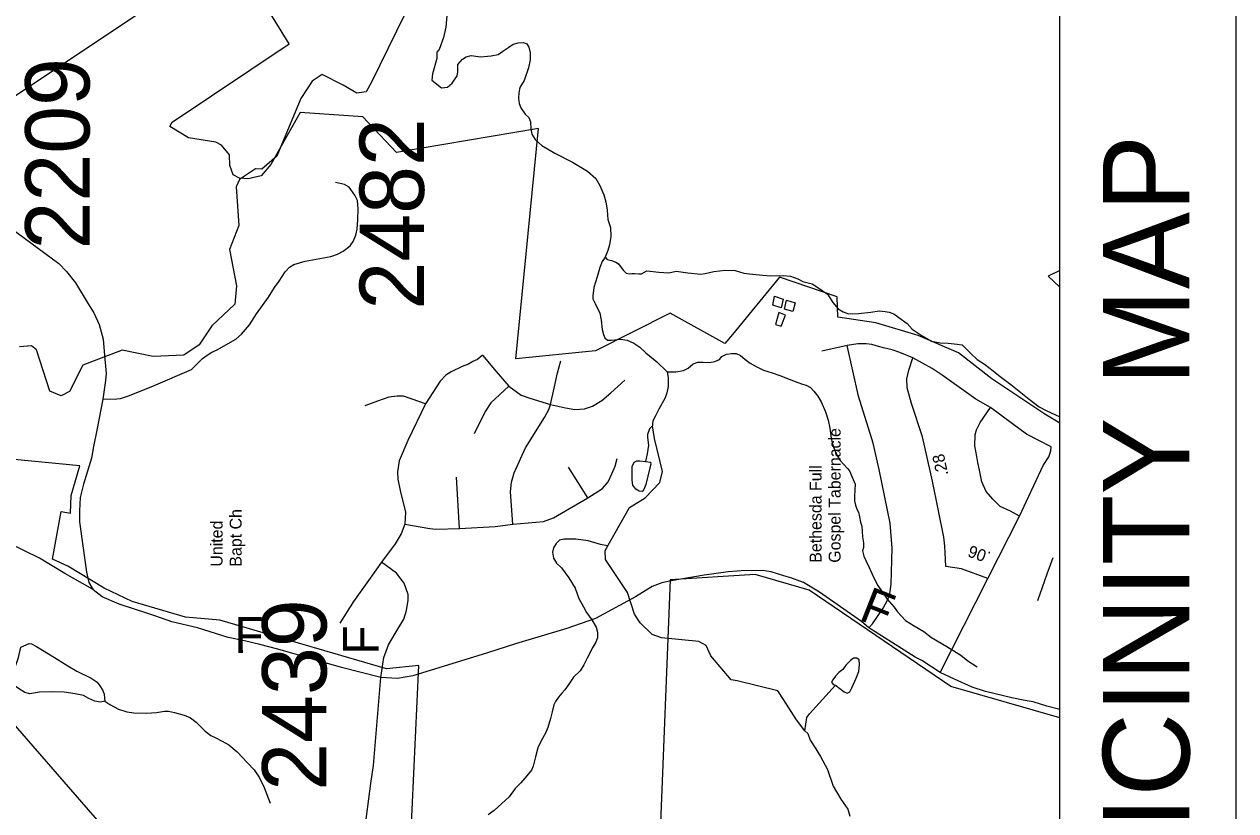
# Model space of a CAD drawing. Extents: x 1373043 to 1375788, y 550128 to 553055.
# Drawn here: x 1373360.4 to 1373623.1, y 550588.9 to 550759.4 of the extents above; entities that cross this region are included whole.
import ezdxf

# ---------------------------------------------------------------- set-up
doc = ezdxf.new("R2010")
doc.units = 0
for name, color, linetype in [('Old_Level_12', 7, 'Continuous'), ('Old_Level_17', 7, 'Continuous'), ('Old_Level_22', 7, 'Continuous'), ('Old_Level_32', 7, 'Continuous'), ('Old_Level_48', 7, 'Continuous'), ('Old_Level_50', 7, 'Continuous'), ('Old_Level_59', 7, 'Continuous'), ('Old_Level_62', 7, 'Continuous'), ('Prop Dimension', 7, 'Continuous'), ('Prop Dimension Text', 7, 'Continuous')]:
    doc.layers.add(name, color=color, linetype=linetype)

msp = doc.modelspace()

# ---------------------------------------------------------------- linework, layer by layer
at = {"layer": 'Old_Level_22'}
for p, q in [((1373400.86, 550641.82), (1373400.86, 550641.82)), ((1373530.72, 550642.67), (1373530.72, 550642.67))]:
    msp.add_line(p, q, dxfattribs=at)
at = {"layer": 'Old_Level_32'}
for p, q in [((1373538.88, 550689.74), (1373533.34, 550688.52)), ((1373454.83, 550650.13), (1373454.17, 550661.22)), ((1373482.61, 550656.73), (1373478.44, 550663.37)), ((1373569.36, 550639.28), (1373576.19, 550652.74)), ((1373559.03, 550618.87), (1373569.36, 550639.28))]:
    msp.add_line(p, q, dxfattribs=at)
for points in [[(1373328.03, 550758.48), (1373329.18, 550754.77), (1373331.08, 550744.1), (1373332.27, 550739.51), (1373332.66, 550737.41), (1373333.69, 550735.13), (1373334.26, 550733.77), (1373336.1, 550731.94), (1373337.95, 550730.2), (1373339.13, 550729.07), (1373349.95, 550720.77), (1373367.92, 550707.57), (1373369.63, 550705.81), (1373371.59, 550703.35), (1373374.3, 550698.81), (1373375.56, 550696.86), (1373376.72, 550694.35), (1373377.56, 550691.18), (1373377.85, 550687.6)], [(1373377.45, 550678.13), (1373380.49, 550678.2), (1373381.31, 550678.3), (1373383.27, 550678.94), (1373388.47, 550681.04), (1373396.69, 550684.56), (1373399.07, 550686.95), (1373399.91, 550687.57), (1373401.12, 550688.3), (1373402.27, 550688.84), (1373404.63, 550690.24), (1373406.31, 550691.16), (1373407.54, 550692.23), (1373409.25, 550694.29), (1373410.81, 550696.61), (1373413.41, 550700.27), (1373414.71, 550702.38), (1373415.68, 550703.75), (1373417.02, 550705.77), (1373417.97, 550706.75), (1373418.92, 550707.34), (1373421.38, 550708.07), (1373426.91, 550709.07), (1373428.33, 550709.61), (1373429.61, 550710.25), (1373431.13, 550711.42), (1373431.74, 550712.3), (1373432.31, 550713.67), (1373432.6, 550714.99), (1373432.74, 550717.09), (1373432.83, 550719.43), (1373432.69, 550721.19), (1373432.12, 550722.37), (1373430.89, 550724.08), (1373429.89, 550724.66), (1373427.9, 550725.15)], [(1373553.1, 550687.08), (1373550.26, 550688.25), (1373548.6, 550688.84), (1373546.75, 550689.28), (1373545.61, 550689.57), (1373544.19, 550690.01), (1373542.96, 550690.11), (1373541.2, 550690.13), (1373538.88, 550689.74)], [(1373377.85, 550687.6), (1373378.18, 550683.7), (1373378.05, 550682.16), (1373377.45, 550678.13)], [(1373459.81, 550687.69), (1373458.72, 550686.76), (1373457.72, 550686.3), (1373456.73, 550685.71), (1373455.4, 550685.22), (1373452.98, 550684.05), (1373451.84, 550683.36), (1373450.61, 550682.04), (1373447.44, 550677.11)], [(1373459.81, 550687.69), (1373462.79, 550684.12), (1373465.5, 550680.97)], [(1373543.57, 550628.57), (1373544.38, 550629.45), (1373546.65, 550632.82), (1373547.7, 550634.68), (1373548.08, 550635.9), (1373548.41, 550638.01), (1373548.64, 550645.8), (1373548.17, 550651.28), (1373545.8, 550662.88), (1373544.47, 550668.63), (1373541.3, 550678.82), (1373538.88, 550689.74)], [(1373474.55, 550676.98), (1373475.36, 550680.55), (1373476.07, 550683.88), (1373476.78, 550686.42)], [(1373560.21, 550641.84), (1373560.16, 550643.36), (1373560, 550646.28), (1373559.78, 550648.25), (1373557.32, 550660.39), (1373555.19, 550669.95), (1373552.77, 550677.2), (1373551.87, 550680.63), (1373551.82, 550682.53), (1373552.2, 550684.44), (1373553.1, 550687.08)], [(1373569.92, 550676.34), (1373566.74, 550678.17), (1373559.48, 550683.37), (1373557.3, 550684.8), (1373553.1, 550687.08)], [(1373474.55, 550676.98), (1373477.77, 550676.25), (1373479.81, 550675.91), (1373481.9, 550676.01), (1373483.65, 550676.59), (1373485.69, 550677.84), (1373487.59, 550679.5), (1373490.62, 550682.29)], [(1373465.5, 550680.97), (1373461.61, 550677.35), (1373460.38, 550675.49), (1373458.01, 550670.61)], [(1373465.5, 550680.97), (1373468.15, 550679.01), (1373470.05, 550678.33), (1373474.55, 550676.98)], [(1373377.45, 550678.13), (1373376.17, 550671.42), (1373375.43, 550667.9), (1373375.01, 550665.35), (1373373.3, 550659.68), (1373372.54, 550656.8), (1373372.44, 550653.89), (1373372.44, 550651.56), (1373373.96, 550640.62), (1373374.46, 550638.4), (1373375.41, 550636.79)], [(1373447.44, 550677.11), (1373444.54, 550678.16), (1373442.65, 550678.79), (1373441.27, 550678.79), (1373439.47, 550678.6), (1373437.05, 550677.67), (1373434.3, 550676.72)], [(1373447.44, 550677.11), (1373443.64, 550669.19), (1373441.75, 550664.79), (1373441.37, 550662.35), (1373441.46, 550660.78), (1373441.94, 550658.34), (1373443.08, 550653.65), (1373442.98, 550651.01)], [(1373466.4, 550651.01), (1373465.88, 550658.02), (1373466.11, 550660.12), (1373466.68, 550662.17), (1373469.15, 550667.6), (1373473.27, 550674.15), (1373474.17, 550675.91), (1373474.55, 550676.98)], [(1373576.19, 550652.74), (1373574.24, 550653.82), (1373572.01, 550654.84), (1373570.4, 550656.46), (1373568.98, 550658.12), (1373568.03, 550660.22), (1373567.51, 550662.76), (1373567.15, 550664.42), (1373566.93, 550665.69), (1373566.56, 550667.99), (1373566.61, 550670.44), (1373566.89, 550671.46), (1373567.7, 550673.07), (1373569.92, 550676.34)], [(1373583.11, 550667.82), (1373577.7, 550670.56), (1373574.72, 550672.81), (1373569.92, 550676.34)], [(1373576.19, 550652.74), (1373581.31, 550663.72), (1373582.54, 550665.67), (1373583.01, 550666.94), (1373583.11, 550667.82)], [(1373482.61, 550656.73), (1373485.83, 550658.8), (1373487.07, 550660.22), (1373487.83, 550661.93), (1373488.54, 550663.64), (1373488.96, 550665.3)], [(1373466.4, 550651.01), (1373473.04, 550651.64), (1373475.17, 550652.42), (1373482.61, 550656.73)], [(1373442.98, 550651.01), (1373442.18, 550648.93), (1373440.85, 550646.78), (1373437.91, 550642.77)], [(1373442.98, 550651.01), (1373448.39, 550650.13), (1373449.71, 550649.93), (1373454.83, 550650.13)], [(1373454.83, 550650.13), (1373462.51, 550650.52), (1373466.4, 550651.01)], [(1373375.41, 550636.79), (1373374.72, 550637.22), (1373369.24, 550640.36), (1373363.78, 550643.64), (1373357.11, 550646.91), (1373353.57, 550647.68), (1373352.78, 550647.81), (1373350.43, 550648.19), (1373347.78, 550648.18), (1373344.63, 550647.87), (1373343.61, 550647.64), (1373342.66, 550647.34), (1373341.51, 550646.73), (1373338.9, 550645.72), (1373337.63, 550645.12), (1373333.58, 550644), (1373322.27, 550642.97), (1373318.17, 550642.73)], [(1373583.46, 550643.74), (1373582.16, 550640.21), (1373580.15, 550634.42)], [(1373437.91, 550642.77), (1373435.44, 550639.35), (1373431.84, 550634.27), (1373428.9, 550629.57)], [(1373437.72, 550617.75), (1373438.38, 550622.14), (1373439.43, 550624.88), (1373440.85, 550627.33), (1373442.75, 550630.4), (1373443.34, 550632.33), (1373443.68, 550634.59), (1373443.68, 550635.76), (1373442.84, 550638.27), (1373441.13, 550640.42), (1373437.91, 550642.77)], [(1373543.57, 550628.57), (1373541.98, 550629.96), (1373532.85, 550636.27), (1373529.36, 550638.42), (1373526.67, 550639.42), (1373525.1, 550639.83), (1373522.38, 550640.67), (1373520.49, 550641.01), (1373515.89, 550640.91), (1373515, 550640.84), (1373513.04, 550640.67), (1373507.88, 550639.99), (1373500.67, 550638.78), (1373498.66, 550638.28), (1373496.59, 550637.54), (1373492.94, 550635.29), (1373484.32, 550630.58), (1373478.11, 550628.38), (1373466.97, 550625.05), (1373460.85, 550623.15), (1373444.68, 550618.16), (1373441.33, 550617.57), (1373437.72, 550617.75)], [(1373569.36, 550639.28), (1373563.67, 550641.33), (1373560.21, 550641.84)], [(1373437.72, 550617.75), (1373429.26, 550619.98), (1373415.41, 550623.9), (1373411.52, 550624.92), (1373408.23, 550625.7), (1373404.63, 550626.46), (1373398, 550628.55), (1373392.47, 550629.86), (1373388.98, 550631.07), (1373387.22, 550631.66), (1373381.01, 550633.67), (1373377.32, 550635.26), (1373375.41, 550636.79)], [(1373559.03, 550618.87), (1373555.04, 550621.44), (1373553.6, 550622.16), (1373551.99, 550623.2), (1373543.57, 550628.57)], [(1373433.95, 550582.11), (1373435.62, 550594.77), (1373436.13, 550598.71), (1373437.72, 550617.75)], [(1373584.98, 550610.88), (1373582.16, 550611.54), (1373579.17, 550612.52), (1373577.04, 550612.86), (1373574.53, 550613.35), (1373568.84, 550614.72), (1373565.95, 550615.69), (1373562.15, 550617.4), (1373559.03, 550618.87)]]:
    msp.add_lwpolyline(points, dxfattribs=at)
at = {"layer": 'Old_Level_48'}
for points in [[(1373524.15, 550704.61), (1373514.02, 550692.19), (1373512.31, 550690.18), (1373500.47, 550696.79), (1373484.28, 550688.61), (1373467.02, 550686.86), (1373471.9, 550736.81), (1373441.16, 550731.65), (1373433.88, 550739.36), (1373420.29, 550740.28), (1373413.94, 550729), (1373411.81, 550726.59), (1373409.02, 550725.89), (1373407.13, 550726.05), (1373405.77, 550726.77), (1373404.99, 550728.81), (1373404.97, 550731.14), (1373403.18, 550733.2), (1373402, 550733.85), (1373396.09, 550734.79), (1373391.99, 550737.27), (1373392.51, 550738.21), (1373417.89, 550755.2), (1373405.51, 550775.31), (1373351.12, 550739)], [(1373584.98, 550706.07), (1373582.46, 550704.79), (1373584.98, 550702.45)], [(1373584.98, 550672.97), (1373581.69, 550674.91), (1373574.37, 550679.8), (1373570.24, 550682.56), (1373562.98, 550688.22), (1373554.26, 550691.92), (1373545.04, 550694.7), (1373536.85, 550695.92), (1373536.67, 550700.34), (1373524.15, 550704.61)], [(1373444.19, 550581.38), (1373445.99, 550620.38), (1373438.95, 550619.66), (1373402.82, 550630.25), (1373395.39, 550630.86), (1373383.87, 550634.28), (1373377.76, 550637.19), (1373369.89, 550641.91), (1373366.59, 550643.47), (1373368.45, 550653.8), (1373370.47, 550653.45), (1373370.64, 550657.26), (1373372.48, 550663.67), (1373351.49, 550665.74)], [(1373584.98, 550609.04), (1373561.35, 550615.82), (1373530.64, 550636.75), (1373518.91, 550640.1), (1373500.48, 550638.99), (1373498.24, 550582.6)]]:
    msp.add_lwpolyline(points, dxfattribs=at)
at = {"layer": 'Old_Level_50'}
msp.add_line((1373377.84, 550687.6), (1373377.84, 550687.6), dxfattribs=at)
at = {"layer": 'Old_Level_59'}
for points in [[(1373446.58, 550769.04), (1373435.73, 550746.85), (1373434.56, 550744.79), (1373432.54, 550744.51), (1373429.59, 550746.25), (1373425.02, 550748.54), (1373422.86, 550747.06), (1373420.44, 550743.3), (1373415.2, 550730.84), (1373411.94, 550728.04), (1373410.59, 550728.07), (1373407.14, 550725.77), (1373406.38, 550724.2), (1373406.94, 550715.79), (1373404.97, 550710.59), (1373406.46, 550702.68), (1373406.07, 550698.74), (1373401.09, 550694.03), (1373398.39, 550689.9), (1373395.07, 550687.65), (1373388.41, 550687.38), (1373381.68, 550688.76), (1373373.17, 550685.48), (1373370.23, 550679.78), (1373368.46, 550678.89), (1373365.99, 550679.87), (1373363.07, 550688.85), (1373362.05, 550689.67), (1373359.45, 550689.51)], [(1373452.12, 550762.11), (1373451.87, 550758.78), (1373451.31, 550756.59), (1373450.43, 550753.96), (1373449.89, 550753.38), (1373449.89, 550752.03), (1373448.95, 550748.67), (1373448.81, 550747.33), (1373450.87, 550745.68), (1373452.24, 550745.77), (1373453.25, 550746.66), (1373454.32, 550748.27), (1373454.46, 550749.08), (1373454.48, 550750.72), (1373455.43, 550751.84), (1373456.22, 550752.39), (1373457.33, 550752.68), (1373459.37, 550752.39), (1373461.7, 550752.59), (1373463.16, 550752.87), (1373464.23, 550753.61), (1373465.51, 550754.46), (1373466.41, 550755.14), (1373467.5, 550755.43), (1373468.69, 550755.47), (1373469.38, 550755.2), (1373469.86, 550754.5), (1373470.14, 550753.23), (1373470.11, 550751.72), (1373469.76, 550749.96), (1373468.83, 550747.27), (1373467.92, 550745.71), (1373467.64, 550744.59), (1373467.57, 550743.39), (1373467.72, 550742.25), (1373468.07, 550741.3), (1373469.05, 550739.96), (1373469.81, 550739.18), (1373470.23, 550738.29), (1373470.25, 550736.72), (1373470.48, 550735.58), (1373471.21, 550734.43), (1373472.63, 550733.14), (1373475.49, 550731.5), (1373479.31, 550729.53), (1373482.55, 550727.57), (1373484.4, 550725.96), (1373485.2, 550724.49), (1373486.09, 550722.46), (1373486.5, 550720.94), (1373486.85, 550719.1), (1373486.99, 550717.08), (1373487.53, 550715.37), (1373487.61, 550713.41), (1373487.32, 550711.59), (1373486.99, 550710.34), (1373486.39, 550708.9)], [(1373486.39, 550708.9), (1373485.72, 550707.97), (1373485.26, 550706.72), (1373484.65, 550704.65), (1373483.9, 550702.33), (1373483.69, 550700.57), (1373483.72, 550699.88), (1373484.22, 550698.86), (1373485.24, 550696.82), (1373485.52, 550695.3), (1373485.74, 550693.22), (1373486.02, 550692.14), (1373486.32, 550691.44), (1373486.88, 550690.92), (1373487.78, 550690.91), (1373489.73, 550691.12), (1373491.17, 550690.9), (1373492.6, 550690.3), (1373493.91, 550689.45), (1373495.22, 550688.17), (1373497.56, 550686.23), (1373499.8, 550684.1)], [(1373499.8, 550684.1), (1373500.03, 550682.84), (1373500.04, 550680.88), (1373499.75, 550679.5), (1373499.37, 550678.44), (1373498.05, 550675.94), (1373497.2, 550674.39), (1373496.74, 550673.45), (1373496.67, 550672.76), (1373496.66, 550672.38)], [(1373529.66, 550606.25), (1373527.84, 550608.59), (1373525.05, 550612.99), (1373523.79, 550614.88), (1373514.98, 550617.03), (1373513.73, 550617.3), (1373509.28, 550622.47), (1373508.29, 550624.71), (1373506.67, 550625.61), (1373498.61, 550626.42), (1373496.6, 550627.14), (1373494, 550629.65), (1373492.74, 550631.54), (1373491.21, 550636.21), (1373486.45, 550643.4), (1373486.37, 550645.35), (1373491.63, 550654.68), (1373495.08, 550656.72), (1373498.25, 550660.06), (1373498.81, 550662.42), (1373497.11, 550669.64), (1373496.66, 550672.38)], [(1373529.66, 550606.25), (1373530.36, 550605.62), (1373530.8, 550604.19), (1373532.06, 550602.3), (1373532.51, 550601.58), (1373533.05, 550600.68), (1373534.58, 550597.81), (1373535.84, 550594.21), (1373537.46, 550591.43), (1373538.98, 550589.27), (1373539.43, 550587.75)]]:
    msp.add_lwpolyline(points, dxfattribs=at)
at = {"layer": 'Old_Level_62'}
for points in [[(1373486.39, 550708.9), (1373486.82, 550708.39), (1373487.74, 550708.18), (1373488.69, 550707.84), (1373489.31, 550707.45), (1373490.29, 550706.11), (1373490.92, 550705.46), (1373491.59, 550705.32), (1373492.16, 550705.37), (1373492.73, 550705.36), (1373493.68, 550705.28), (1373494.3, 550705.33), (1373495.4, 550705.94), (1373496.15, 550705.86), (1373498.03, 550705.7), (1373500.17, 550705.52), (1373501.81, 550705.87), (1373504.34, 550705.5), (1373507.1, 550705.25), (1373508.06, 550705.42), (1373509.95, 550705.82), (1373512.41, 550706.09), (1373514.56, 550706.04), (1373516.43, 550705.44), (1373518.31, 550705.21), (1373520.59, 550705.04), (1373522.29, 550704.87), (1373525.06, 550704.94), (1373526.58, 550704.79), (1373528.19, 550704.25), (1373529.27, 550703.66), (1373531.28, 550703.18), (1373532.5, 550702.33), (1373534.56, 550700.9), (1373535.72, 550699.11), (1373536.88, 550697.76), (1373537.95, 550697.05), (1373539.13, 550696.65), (1373541.33, 550696.73), (1373544, 550696.99), (1373545.76, 550697.26), (1373547.08, 550697.18), (1373547.95, 550696.97), (1373548.95, 550696.63), (1373550.07, 550695.85), (1373551.83, 550694.56), (1373552.92, 550693.34), (1373554.91, 550692.03), (1373557.11, 550690.73), (1373558.99, 550690.37), (1373560.74, 550690.27), (1373562.7, 550690.1), (1373563.76, 550689.9), (1373564.75, 550688.99), (1373565.68, 550688.03), (1373567.03, 550686.74), (1373568.66, 550685.76), (1373570.52, 550684.27), (1373572, 550683.04), (1373574.31, 550681.29), (1373578.33, 550678.12), (1373580.5, 550676.5), (1373582.01, 550675.71), (1373584.98, 550674.29)], [(1373522.73, 550698.5), (1373523.08, 550700.45), (1373524.95, 550699.84), (1373524.53, 550697.96), (1373522.73, 550698.5)], [(1373525.3, 550697.63), (1373525.7, 550699.57), (1373527.57, 550699.03), (1373527.04, 550697.15), (1373525.3, 550697.63)], [(1373524.07, 550696.9), (1373523.32, 550694.33), (1373524.58, 550693.99), (1373525.45, 550696.36), (1373524.07, 550696.9)], [(1373499.8, 550684.1), (1373501.68, 550684.06), (1373503.34, 550684.35), (1373504.36, 550684.83), (1373505.49, 550685.81), (1373506.45, 550686.17), (1373507.64, 550686.14), (1373509.04, 550686.12), (1373510.18, 550686.34), (1373511.14, 550686.76), (1373511.65, 550687.38), (1373512.72, 550687.93), (1373513.81, 550688.03), (1373514.76, 550688.01), (1373515.76, 550687.62), (1373516.68, 550686.84), (1373517.8, 550685.93), (1373519.1, 550685.21), (1373520.74, 550684.42), (1373522.61, 550683.82), (1373524.23, 550683.28), (1373526.31, 550682.48), (1373528.18, 550681.75), (1373529.18, 550681.41), (1373529.98, 550681.14), (1373530.93, 550680.68), (1373531.66, 550679.85), (1373532.52, 550678.76), (1373533.24, 550677.54), (1373534.15, 550675.38), (1373534.74, 550673.6), (1373535.09, 550671.83), (1373535.36, 550669.69), (1373535.59, 550668.67), (1373535.94, 550667.59), (1373536.73, 550665.81), (1373537.33, 550664.85), (1373538.14, 550663.96), (1373538.95, 550663.12), (1373539.38, 550662.61), (1373539.97, 550661.21), (1373540.58, 550659.68), (1373540.45, 550657.1), (1373540.43, 550656.09), (1373540.67, 550655.14), (1373540.97, 550654.32), (1373541.34, 550653.61), (1373541.55, 550652.6), (1373541.74, 550651.46), (1373542.03, 550650.57), (1373542.16, 550648.3), (1373542.4, 550646.98), (1373542.38, 550645.97), (1373542.15, 550645.22), (1373542.47, 550644.08), (1373542.89, 550643.12), (1373543.61, 550641.65), (1373544.57, 550639.55), (1373545.47, 550637.71), (1373546.45, 550636.36), (1373547.5, 550634.77), (1373549.04, 550633.03), (1373549.77, 550632.01), (1373551.49, 550630.14), (1373553.36, 550628.97), (1373555.48, 550627.73), (1373557.16, 550626.44), (1373560.45, 550624.54), (1373563.49, 550622.65), (1373565.04, 550621.42), (1373567.03, 550620.12)], [(1373496.66, 550672.38), (1373496, 550671.7), (1373495.54, 550670.51), (1373495.53, 550669.82), (1373495.75, 550668.18), (1373495.51, 550666.29), (1373495.11, 550664.6)], [(1373495.11, 550664.6), (1373496.25, 550664.45), (1373496.29, 550664.07), (1373496.09, 550663.25), (1373495.62, 550661.43), (1373495.24, 550659.67), (1373494.78, 550658.55), (1373494.41, 550658.12), (1373493.77, 550658.19), (1373493.03, 550658.59), (1373492.42, 550659.48), (1373492.24, 550660.56), (1373492.22, 550662.07), (1373492.25, 550663.52), (1373492.65, 550664.46), (1373493.23, 550664.76), (1373493.9, 550664.75), (1373495.11, 550664.6)], [(1373486.91, 550646.31), (1373485.34, 550646.65), (1373482.72, 550647.4), (1373480.06, 550647.76), (1373477.43, 550647.76), (1373476.47, 550647.59), (1373475.75, 550646.85), (1373475.17, 550645.91), (1373474.97, 550644.97), (1373475.2, 550643.64), (1373475.85, 550642.56), (1373476.92, 550641.59), (1373478.5, 550639.42), (1373479.85, 550637.12), (1373480.68, 550634.89), (1373481.66, 550633.11), (1373482.33, 550631.9), (1373483.49, 550630.3), (1373484.46, 550628.7), (1373484.7, 550627.63), (1373484.73, 550626.36), (1373484.4, 550625.43), (1373483.68, 550624.37), (1373482.49, 550622), (1373481.76, 550620.5), (1373480.99, 550619.25), (1373479.51, 550617.84), (1373478.48, 550616.35), (1373477.67, 550615.1), (1373476.99, 550614.36), (1373476.27, 550613.49), (1373475.61, 550612.56), (1373475.23, 550611.87), (1373474.89, 550610.37), (1373474.53, 550608.86), (1373473.99, 550606.92), (1373473.59, 550605.99), (1373472.35, 550603.74), (1373471.76, 550602.5), (1373471.28, 550600.61), (1373470.78, 550598.54), (1373470.4, 550597.67), (1373469.41, 550596.43), (1373468.12, 550594.94), (1373466.9, 550593.71), (1373465.6, 550591.91), (1373464, 550590.49), (1373462.34, 550588.95), (1373461.05, 550588.03)], [(1373359.18, 550622.09), (1373359.72, 550624.37), (1373361.53, 550625.14), (1373362.05, 550625.07), (1373363.09, 550624.48), (1373367.03, 550622.13), (1373369.89, 550620.3), (1373371.88, 550619.19), (1373374.92, 550617.62), (1373376.25, 550616.77), (1373376.86, 550616), (1373377.46, 550614.98), (1373377.77, 550614.15), (1373377.81, 550613.27), (1373377.92, 550612.64)], [(1373377.92, 550612.64), (1373376.96, 550612.47), (1373375.78, 550612.62), (1373374.47, 550613.21), (1373373.27, 550613.87), (1373371.47, 550614.22), (1373369.12, 550614.58), (1373366.57, 550614.7), (1373363.77, 550614.57), (1373361.63, 550614.27), (1373360.55, 550614.54), (1373359.19, 550615.42), (1373358.5, 550615.94), (1373357.97, 550616.18), (1373357.56, 550617.79), (1373358.37, 550619.81), (1373359.18, 550622.09)], [(1373536.32, 550616.09), (1373538.18, 550614.66), (1373538.82, 550614.4), (1373539.45, 550614.7), (1373539.9, 550615.57), (1373540.82, 550617.64), (1373541.37, 550619.07), (1373541.53, 550620.71), (1373541.42, 550621.59), (1373540.94, 550621.98), (1373540.24, 550622), (1373539.58, 550621.5), (1373538.55, 550620.46), (1373537.92, 550619.52), (1373537.02, 550618.85), (1373536.31, 550618.04), (1373535.78, 550617.3), (1373535.46, 550616.8), (1373535.83, 550616.29), (1373536.32, 550616.09)], [(1373529.66, 550606.25), (1373530.09, 550609.13), (1373530.72, 550609.93), (1373536.32, 550616.09)], [(1373377.92, 550612.64), (1373378.97, 550611.92), (1373380.91, 550610.93), (1373382.66, 550610.33), (1373384.23, 550610.11), (1373386.95, 550610.06), (1373389.09, 550610.2), (1373390.86, 550610.48), (1373391.69, 550610.46), (1373393.05, 550610.18), (1373395.13, 550609.63), (1373396.52, 550609.04), (1373397.74, 550608.07), (1373399.66, 550606.13), (1373400.91, 550605.22), (1373402.01, 550604.7), (1373403.39, 550603.97), (1373404.82, 550603.19), (1373406.63, 550601.7), (1373408.86, 550599.26), (1373410.27, 550597.78), (1373411.48, 550596.06), (1373412.44, 550593.95), (1373413.77, 550590.52)]]:
    msp.add_lwpolyline(points, dxfattribs=at)
at = {"layer": 'Prop Dimension'}
msp.add_line((1373327.17, 550643.23), (1373389.2, 550572.03), dxfattribs=at)
at = {"layer": 'Prop Dimension Text'}
for points in [[(1373088.48, 550913.04), (1373088.48, 550416.54), (1373584.98, 550416.54), (1373584.98, 550913.04)], [(1373623.1, 550913.04), (1373623.1, 550416.54), (1373584.98, 550416.54), (1373584.98, 550913.04)]]:
    msp.add_lwpolyline(points, close=True, dxfattribs=at)

# ---------------------------------------------------------------- texts
at = {"layer": 'Old_Level_12'}
for s, p in [('2209', (1373374.61, 550710.6)), ('2482', (1373447.1, 550697.56)), ('2439', (1373425.97, 550593.23))]:
    msp.add_text(s, height=13.952, rotation=90, dxfattribs=at).set_placement(p)
at = {"layer": 'Old_Level_17'}
for s, rotation, p in [('.28', 102.5848, (1373560.81, 550661.79)), ('.06', 160.2006, (1373570.18, 550644.9))]:
    msp.add_text(s, height=2.584, rotation=rotation, dxfattribs=at).set_placement(p)
at = {"layer": 'Old_Level_22'}
for s, height, rotation, p in [('Gospel Tabernacle', 2.5837, 90, (1373537.43, 550642.67)), ('Bethesda Full', 2.5837, 90, (1373533.3, 550642.67)), ('Bapt Ch', 2.584, 90, (1373407.57, 550641.82)), ('United ', 2.584, 90, (1373403.44, 550641.82)), ('F', 7.75, 338.5023, (1373541.13, 550630.38)), ('F', 7.75, 0.1953, (1373406.02, 550623.12)), ('F', 7.75, 90, (1373437.3, 550622.76))]:
    msp.add_text(s, height=height, rotation=rotation, dxfattribs=at).set_placement(p)
at = {"layer": 'Prop Dimension Text'}
msp.add_text('VICINITY MAP', height=18.7502, rotation=90, dxfattribs=at).set_placement((1373613.05, 550568.28))

doc.saveas('drawing.dxf')
